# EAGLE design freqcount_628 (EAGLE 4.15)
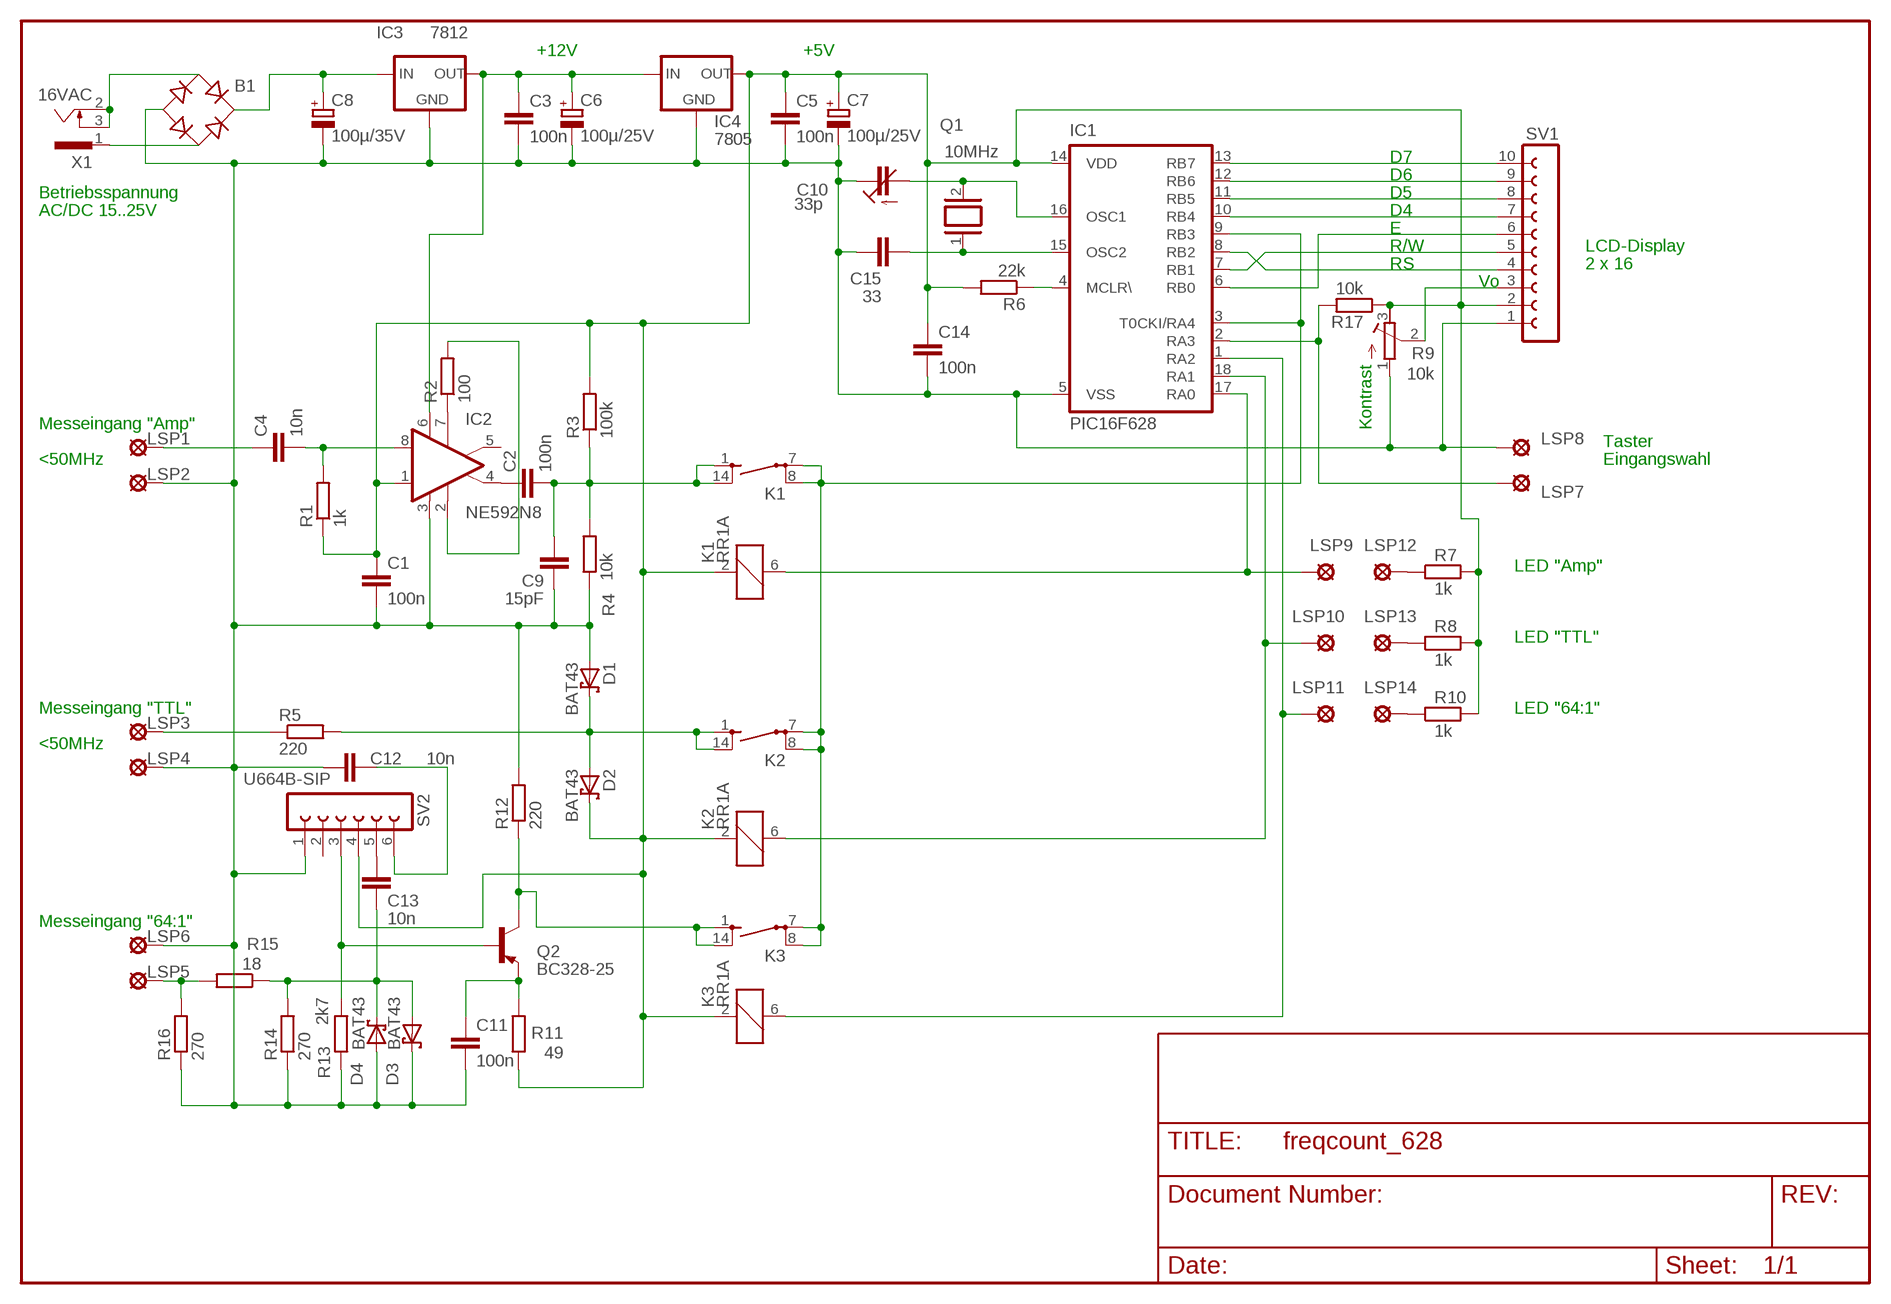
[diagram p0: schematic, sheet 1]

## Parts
B1  RB1A  [RB1A]
C1  100n  C-EU050-025X075  [C050-025X075]
C2  100n  C-EU050-025X075  [C050-025X075]
C3  100n  C-EU050-025X075  [C050-025X075]
C4  10n  C-EU050-025X075  [C050-025X075]
C5  100n  C-EU050-025X075  [C050-025X075]
C6  100µ/25V  CPOL-EUE5-8.5  [E5-8,5]
C7  100µ/25V  CPOL-EUE5-8.5  [E5-8,5]
C8  100µ/35V  CPOL-EUE5-8.5  [E5-8,5]
C9  15pF  C-EU050-025X075  [C050-025X075]
C10  33p  C-TRIMM3040.427  [CTRIM3040.427]
C11  100n  C-EU050-025X075  [C050-025X075]
C12  10n  C-EU050-025X075  [C050-025X075]
C13  10n  C-EU050-025X075  [C050-025X075]
C14  100n  C-EU050-025X075  [C050-025X075]
C15  33  C-EU025-025X050  [C025-025X050]
D1  BAT43  [DO35-10]
D2  BAT43  [DO35-10]
D3  BAT43  [DO35-10]
D4  BAT43  [DO35-10]
IC1  PIC16F628  PIC16F84AP  [DIL18]
IC2  NE592N8  [DIL08]
IC3  7812  78XXS  [78XXS]
IC4  7805  78XXS  [78XXS]
K1  RR1A  [RR1A]
K2  RR1A  [RR1A]
K3  RR1A  [RR1A]
LSP1  LSP10  [LSP10]
LSP2  LSP10  [LSP10]
LSP3  LSP10  [LSP10]
LSP4  LSP10  [LSP10]
LSP5  LSP10  [LSP10]
LSP6  LSP10  [LSP10]
LSP7  LSP10  [LSP10]
LSP8  LSP10  [LSP10]
LSP9  LSP10  [LSP10]
LSP10  LSP10  [LSP10]
LSP11  LSP10  [LSP10]
LSP12  LSP10  [LSP10]
LSP13  LSP10  [LSP10]
LSP14  LSP10  [LSP10]
Q1  10MHz  XTAL/S  [QS]
Q2  BC328-25  [TO92-EBC]
R1  1k  R-EU_0207/10  [0207/10]
R2  100  R-EU_0207/10  [0207/10]
R3  100k  R-EU_0207/10  [0207/10]
R4  10k  R-EU_0207/10  [0207/10]
R5  220  R-EU_0207/10  [0207/10]
R6  22k  R-EU_0207/10  [0207/10]
R7  1k  R-EU_0207/10  [0207/10]
R8  1k  R-EU_0207/10  [0207/10]
R9  10k  R-TRIMM3339P  [RTRIM3339P]
R10  1k  R-EU_0207/10  [0207/10]
R11  49  R-EU_0207/10  [0207/10]
R12  220  R-EU_0207/10  [0207/10]
R13  2k7  R-EU_0207/10  [0207/10]
R14  270  R-EU_0207/10  [0207/10]
R15  18  R-EU_0207/10  [0207/10]
R16  270  R-EU_0207/10  [0207/10]
R17  10k  R-EU_0207/10  [0207/10]
SV1  FE10-1  [FE10]
SV2  U664B-SIP  FE06-1  [FE06]
X1  16VAC  733989-55  [733989-5]

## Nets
5VDC: C1.1 C5.1 C7.+ C14.1 D2.C IC1.14(VDD) IC2.1(IN2) IC4.OUT K1.2 K2.2 K3.2 R1.1 R3.2 R6.2 R7.2 R8.2 R9.3(A) R10.2 R11.1 R17.1 SV1.2 SV2.4
12VDC: C3.1 C6.+ IC2.6(V+) IC3.OUT IC4.IN
GND: B1.- C1.2 C3.2 C5.2 C6.- C7.- C8.- C9.1 C10.1A(E) C11.2 C12.1 C14.2 C15.1 D1.A D3.C D4.A IC1.5(VSS) IC2.3(V-) IC3.GND IC4.GND LSP2.MP LSP4.MP LSP6.MP LSP8.MP R4.1 R9.1(E) R12.2 R13.1 R14.1 R16.1 SV1.1 SV2.1
N$1: C4.2 IC2.8(IN1) R1.2
N$2: C4.1 LSP1.MP
N$3: C2.1 IC2.4(OUT2)
N$5: IC2.7(G1A) R2.1
N$6: IC2.2(G1B) R2.2
N$7: LSP3.MP R5.1
N$8: C2.2 C9.2 K1.1(2:S) K1.14(2:S) R3.1 R4.2
N$9: D1.C D2.A K2.1(2:S) K2.14(2:S) R5.2
N$10: C15.2 IC1.15(OSC2) Q1.1
N$11: C10.2(A) IC1.16(OSC1) Q1.2
N$12: B1.+ C8.+ IC3.IN
N$13: IC1.4(MCLR\) R6.1
N$14: IC1.13(RB7) SV1.10
N$15: IC1.12(RB6) SV1.9
N$16: B1.AC2 X1.1
N$17: B1.AC1 X1.2 X1.3
N$18: IC1.11(RB5) SV1.8
N$19: IC1.10(RB4) SV1.7
N$20: R9.2(S) SV1.3
N$21: IC1.8(RB2) SV1.4
N$22: IC1.7(RB1) SV1.5
N$23: IC1.6(RB0) SV1.6
N$24: IC1.17(RA0) K1.6 LSP9.MP
N$25: IC1.18(RA1) K2.6 LSP10.MP
N$26: IC1.1(RA2) K3.6 LSP11.MP
N$27: LSP12.MP R7.1
N$28: C13.2 D3.A D4.C R14.2 R15.1
N$29: LSP13.MP R8.1
N$30: C11.1 Q2.E R11.2
N$31: LSP14.MP R10.1
N$32: K3.1(2:S) K3.14(2:S) Q2.C R12.1
N$33: IC1.2(RA3) LSP7.MP R17.2
N$34: C13.1 SV2.5
N$35: C12.2 SV2.6
N$36: Q2.B R13.2 SV2.3
N$37: LSP5.MP R15.2 R16.2
TAKTRA4: IC1.3(T0CKI/RA4) IC1.9(RB3) K1.7(2:P) K1.8(2:P) K2.7(2:P) K2.8(2:P) K3.7(2:P) K3.8(2:P)
Unconnected: IC2.5(OUT1) SV2.2

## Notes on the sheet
- +12V | +5V
- D7
- D6
- Betriebsspannung | D5
- AC/DC 15..25V | D4
- E
- R/W | LCD-Display
- RS | 2 x 16
- Vo
- Messeingang "Amp" | Kontrast
- Taster
- <50MHz | Eingangswahl
- LED "Amp"
- LED "TTL"
- Messeingang "TTL" | LED "64:1"
- <50MHz
- Messeingang "64:1"

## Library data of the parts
B1 = rectifier:RB1A: RECTIFIER 1 A
C1-C5 C9 C11-C15 = rcl:C-EU: CAPACITOR, European symbol
C6-C8 = rcl:CPOL-EU: POLARIZED CAPACITOR, European symbol
C10 = rcl:C-TRIMM: Trimm capacitor
D1-D4 = sprut:BAT43: DIODE
IC1 = microchip:PIC16F8*: MICROCONTROLLER 8-Bit PIC16F8X Family - CMOS Flash/EEPROM Pin Compatible : PIC16F83, PIC16CR83, PIC16F84A, PIC16CR84 see also PIC16C*
IC2 = linear:NE592?8: VIDEO AMPLIFIER
IC3 IC4 = v-reg:78XXS: VOLTAGE REGULATOR
K1-K3 = relay:RR1A: RELAY reed, polarity, 1 x norm. open with shield
LSP1-LSP14 = solpad:LSP10: SOLDER PAD
Q1 = special:XTAL/S: CRYSTAL
Q2 = transistor-pnp:BC328*: PNP Transistror
R1-R8 R10-R17 = rcl:R-EU_: RESISTOR, European symbol
R9 = rcl:R-TRIMM: Trimm resistor
SV1 = con-lsta:FE10-1: FEMALE HEADER
SV2 = con-lsta:FE06-1: FEMALE HEADER
X1 = con-conrad:733989-55: FEMALE PRINT CONNECTOR 1.1 mm, FUK HING Industries, distributor Conrad

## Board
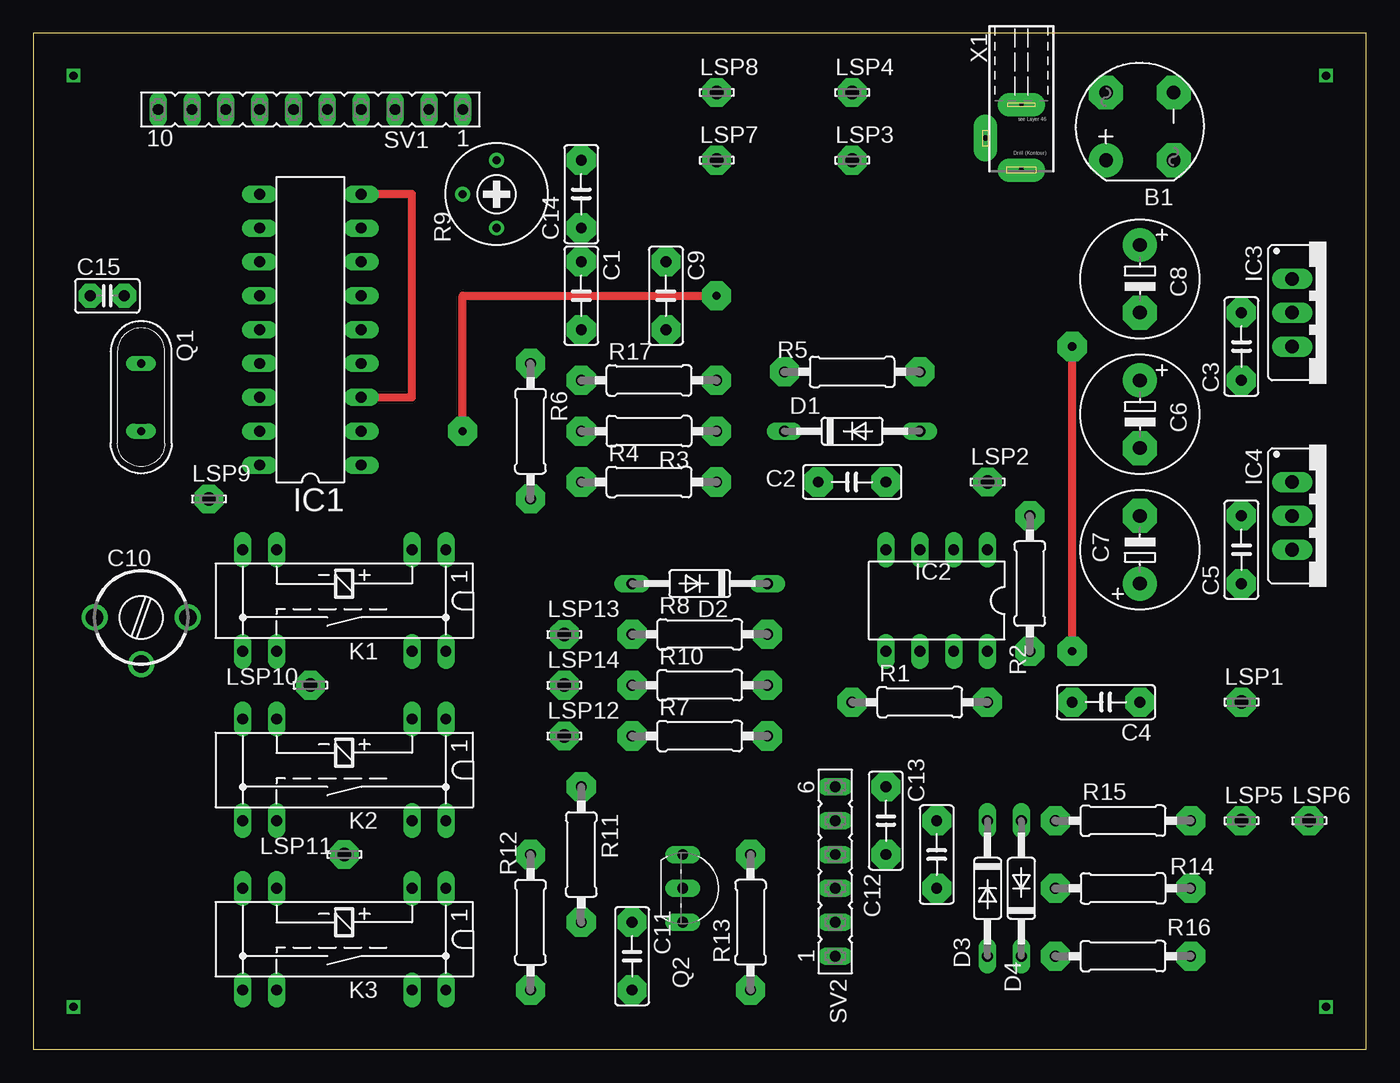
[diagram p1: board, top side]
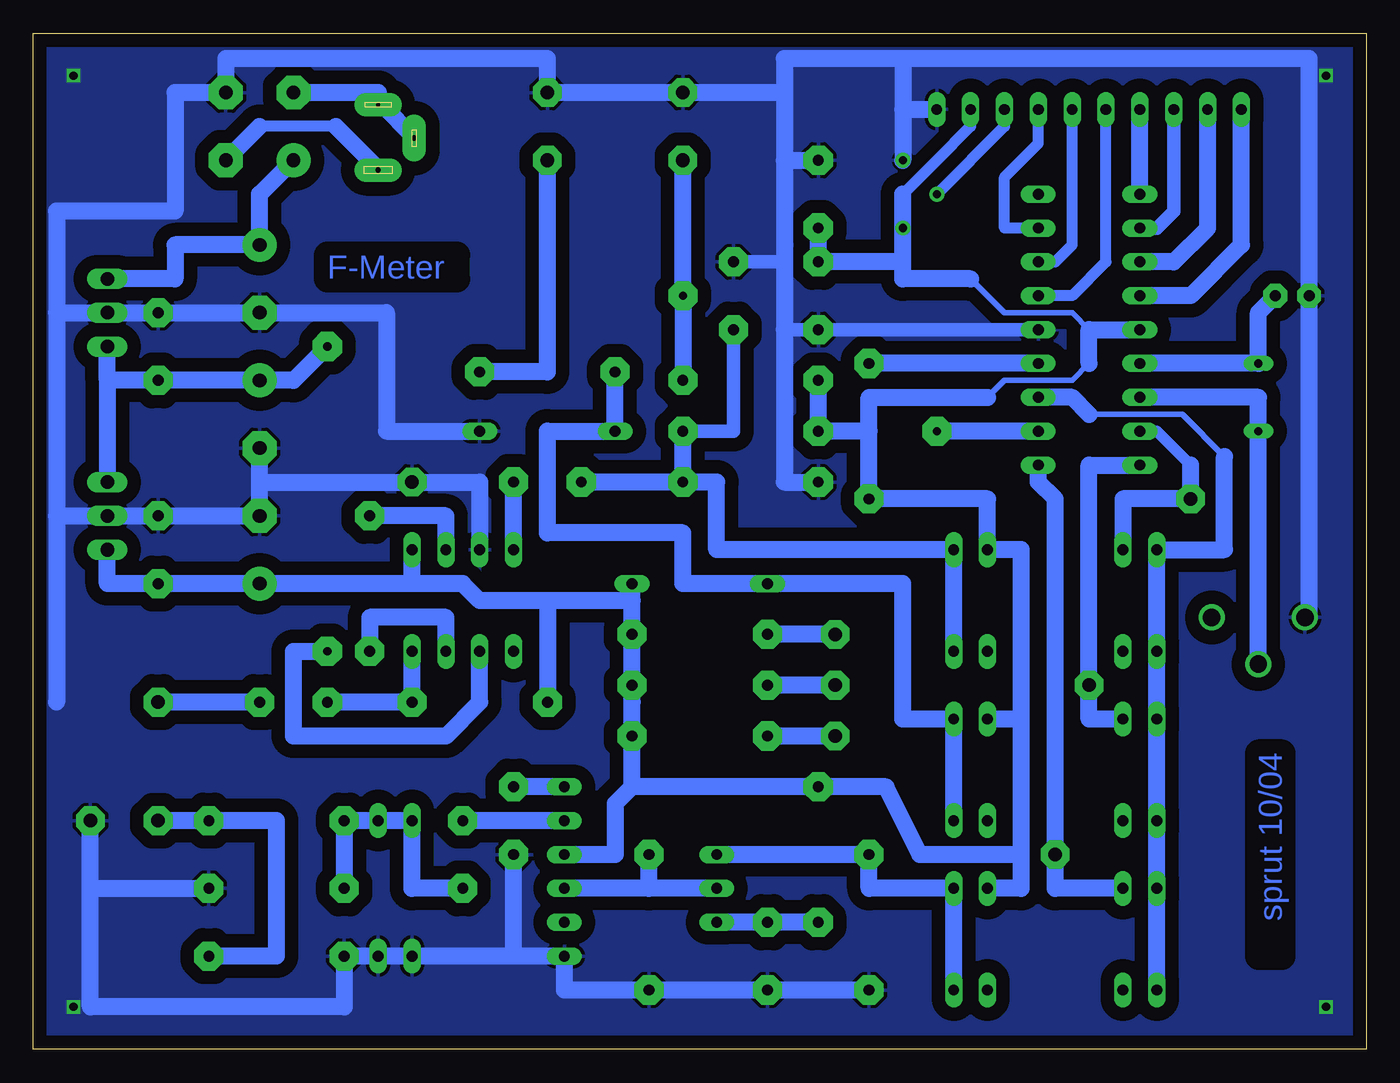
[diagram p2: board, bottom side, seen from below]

Size 100 x 76.19 mm. Coordinates in mm from the lower left corner, seen from the top.
Outline: 0,0 100,0 100,76.19 0,76.19 0,0
Copper layers (1*16): Top 0.035mm / dielectric 1.5mm / Bottom 0.035mm
Design rules "default": minimum track width 10mil, minimum drill 24mil, track to track 8mil, track to pad 8mil, pad to pad 8mil, via to via 8mil, smd to smd 8mil, copper to edge 40mil, drill to drill 8mil, minimum pad ring 10mil, minimum via ring 8mil, stop-mask expansion 4mil, vias tented up to drill 0mil, thermal gap 10mil

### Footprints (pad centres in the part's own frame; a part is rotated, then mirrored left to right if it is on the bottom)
RB1A = drill 1.016 pad 2.54 round: + -2.54,2.54 | drill 1.016 pad 2.54 octagon: - 2.54,-2.54; AC1 2.54,2.54; AC2 -2.54,-2.54
C050-025X075 = drill 0.813 pad 2.184 octagon: 1 -2.54,0; 2 2.54,0
E5-8,5 = drill 1.016 pad 2.54 round: + -2.54,0 | drill 1.016 pad 2.54 octagon: - 2.54,0
CTRIM3040.427 = drill 1.3 round: 1A -3.5,0; 1B 3.5,0; 2 0,-3.5
C025-025X050 = drill 0.813 pad 1.778 octagon: 1 -1.27,0; 2 1.27,0
DO35-10 = drill 0.813 long: A 5.08,0; C -5.08,0
DIL18 = drill 0.813 long: 1 -10.16,-3.81; 2 -7.62,-3.81; 3 -5.08,-3.81; 4 -2.54,-3.81; 5 0,-3.81; 6 2.54,-3.81; 7 5.08,-3.81; 8 7.62,-3.81; 9 10.16,-3.81; 10 10.16,3.81; 11 7.62,3.81; 12 5.08,3.81; 13 2.54,3.81; 14 0,3.81; 15 -2.54,3.81; 16 -5.08,3.81; 17 -7.62,3.81; 18 -10.16,3.81
DIL08 = drill 0.813 long: 1 -3.81,-3.81; 2 -1.27,-3.81; 3 1.27,-3.81; 4 3.81,-3.81; 5 3.81,3.81; 6 1.27,3.81; 7 -1.27,3.81; 8 -3.81,3.81
78XXS = drill 1.016 long: GND 0,-2.54; IN -2.54,-2.54; OUT 2.54,-2.54
RR1A = drill 0.813 long: 1 -7.62,-3.81; 2 -5.08,-3.81; 6 5.08,-3.81; 7 7.62,-3.81; 8 7.62,3.81; 9 5.08,3.81; 13 -5.08,3.81; 14 -7.62,3.81
LSP10 = drill 1.016 pad 2.159 octagon: MP 0,0
QS = drill 0.61 long: 1 -2.54,0; 2 2.54,0
TO92-EBC = drill 0.813 long: B 0,-1.27; C -2.54,-1.27; E 2.54,-1.27
0207/10 = drill 0.813 pad 2.184 octagon: 1 -5.08,0; 2 5.08,0
RTRIM3339P = drill 0.61 round: 1 -2.54,0; 2 0,-2.54; 3 2.54,0
FE10 = drill 0.813 long: 1 -11.43,0; 2 -8.89,0; 3 -6.35,0; 4 -3.81,0; 5 -1.27,0; 6 1.27,0; 7 3.81,0; 8 6.35,0; 9 8.89,0; 10 11.43,0
FE06 = drill 0.813 long: 1 -6.35,0; 2 -3.81,0; 3 -1.27,0; 4 1.27,0; 5 3.81,0; 6 6.35,0
733989-5 = drill 0.4 pad 1.778 long: 1 0,5.82; 3 2.7,3.42 | drill 0.3 pad 1.778 long: 2 0,0.92

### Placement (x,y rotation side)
B1  83.02,69.21 90 top
C1  41.11,56.51 270 top
C2  61.43,42.54 180 top
C3  90.64,52.7 90 top
C4  80.48,26.03 180 top
C5  90.64,37.46 90 top
C6  83.02,47.62 270 top
C7  83.02,37.46 90 top
C8  83.02,57.78 270 top
C9  47.46,56.51 270 top
C10  8.09,32.38 0 top
C11  44.92,6.98 270 top
C12  63.97,17.14 90 top
C13  67.78,14.6 270 top
C14  41.11,64.13 90 top
C15  5.55,56.51 0 top
D1  61.43,46.35 0 top
D2  50,34.92 180 top
D3  74.13,12.06 90 top
D4  71.59,12.06 270 top
IC1  20.79,53.97 90 top
IC2  67.78,33.65 180 top
IC3  96.99,55.24 270 top
IC4  96.99,40 270 top
K1  23.33,33.65 180 top
K2  23.33,20.95 180 top
K3  23.33,8.25 180 top
LSP1  90.64,26.03 0 top
LSP2  71.59,42.54 0 top
LSP3  61.43,66.67 0 top
LSP4  61.43,71.75 0 top
LSP5  90.64,17.14 0 top
LSP6  95.72,17.14 0 top
LSP7  51.27,66.67 0 top
LSP8  51.27,71.75 0 top
LSP9  13.17,41.27 0 top
LSP10  20.79,27.3 0 top
LSP11  23.33,14.6 0 top
LSP12  39.84,23.49 0 top
LSP13  39.84,31.11 0 top
LSP14  39.84,27.3 0 top
Q1  8.09,48.89 270 top
Q2  50,12.06 270 top
R1  66.51,26.03 0 top
R2  74.77,34.92 90 top
R3  46.19,46.35 180 top
R4  46.19,42.54 0 top
R5  61.43,50.8 180 top
R6  37.3,46.35 270 top
R7  50,23.49 0 top
R8  50,31.11 0 top
R9  34.76,64.13 270 top
R10  50,27.3 0 top
R11  41.11,14.6 270 top
R12  37.3,9.52 270 top
R13  53.81,9.52 90 top
R14  81.75,12.06 180 top
R15  81.75,17.14 0 top
R16  81.75,6.98 0 top
R17  46.19,50.16 0 top
SV1  20.79,70.48 180 top
SV2  60.16,13.33 90 top
X1  74.13,71.75 180 top

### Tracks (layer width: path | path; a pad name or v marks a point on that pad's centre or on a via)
5VDC
  Bottom 0.406: 55.08,26.03 R10.2 R8.2 | 20.79,51.43 22.06,50.16 27.14,50.16 28.41,48.89 | 20.79,53.97 22.06,55.24 27.14,55.24 29.68,57.78
  Bottom 0.813: SV1.2 29.68,69.21 32.22,66.67 34.76,64.13
  Bottom 1.016: R3.2 R17.1
  Bottom 1.27: 55.08,19.68 R11.1 36.03,19.68 33.49,14.6 25.87,14.6 | 55.08,19.68 R7.2 55.08,26.03 R8.2 55.08,33.65 | IC4.OUT 94.45,34.92 C5.1 C7.+ 71.59,34.92 | R17.1 R3.2 37.3,46.35 | 25.87,14.6 25.87,12.06 K3.2 | 25.87,14.6 25.87,24.76 | 25.87,24.76 K2.2 | 25.87,24.76 25.87,37.46 K1.2 28.41,41.27 R6.2 37.3,46.35 | IC1.14 20.79,53.97 20.79,51.43 | 34.76,64.13 R9.3 34.76,59.05 | 71.59,34.92 IC2.1 | 71.59,34.92 67.78,34.92 66.51,33.65 61.43,33.65 | 55.08,33.65 61.43,33.65 | 55.08,33.65 D2.C | SV2.4 56.35,14.6 56.35,18.41 55.08,19.68 | 29.68,57.78 34.76,57.78 34.76,59.05 | C14.1 C1.1 34.76,59.05 | 28.41,48.89 37.3,48.89 37.3,46.35 | 61.43,33.65 R1.1
12VDC  (via drill 0.61 pad 2.18)
  Top 0.61: v77.94,29.84 v77.94,52.7
  Bottom 1.27: 94.45,50.16 IC3.OUT | 94.45,50.16 C3.1 C6.+ 80.48,50.16 v77.94,52.7 | 94.45,50.16 IC4.IN | IC2.6 66.51,26.03 69.05,23.49 80.48,23.49 80.48,29.84 v77.94,29.84
GND  (via drill 0.61)
  Bottom 0.406: C10.1A 4.28,32.38
  Bottom 1.016: IC1.5 C1.2 43.65,53.97 | 43.65,59.05 C9.1
  Bottom 1.27: 63.97,6.98 SV2.1 60.16,4.44 R13.1 R12.2 C11.2 | 63.97,6.98 D4.A D3.C R16.1 76.67,3.17 95.72,3.17 95.72,12.06 | 63.97,6.98 C12.1 | 95.72,12.06 LSP6.MP | 95.72,12.06 R14.1 | D1.A 73.5,46.35 73.5,55.24 C8.- C3.2 IC3.GND 98.26,55.24 | 83.02,42.54 C7.- C5.2 IC4.GND 98.26,40 | 83.02,42.54 C6.- | 98.26,55.24 98.26,40 | 98.26,40 98.26,26.03 | 43.65,71.75 LSP8.MP LSP4.MP 61.43,74.29 85.56,74.29 B1.- 89.37,71.75 89.37,62.86 98.26,62.86 98.26,55.24 | 43.65,71.75 43.65,66.67 | R4.1 43.65,42.54 43.65,53.97 43.65,59.05 43.65,66.67 | 34.76,70.48 R9.1 | 34.76,74.29 4.28,74.29 C15.1 4.28,32.38 | 34.76,74.29 34.76,70.48 | 34.76,70.48 SV1.1 | 34.76,74.29 43.65,74.29 43.65,71.75 | 43.65,66.67 C14.2 | IC2.3 66.51,42.54 83.02,42.54
  other vias: 3.01,73.02 3.01,3.17 96.99,73.02 96.99,3.17
  pour Bottom (isolate 1.016): -0.8,76.83 100.8,76.83 100.8,-0.64 -0.8,-0.64
N$1
  Bottom 1.27: IC2.8 R1.2 C4.2
N$2
  Bottom 1.27: C4.1 LSP1.MP
N$3
  Bottom 1.27: IC2.4 C2.1
N$5
  Bottom 1.27: IC2.7 69.05,32.38 74.77,32.38 R2.1
N$6
  Bottom 1.27: IC2.2 69.05,40 R2.2
N$7
  Bottom 1.27: LSP3.MP 61.43,50.8 R5.1
N$8
  Bottom 1.016: C9.2 47.46,46.35 R3.1
  Bottom 1.27: R4.2 R3.1 | K1.14 K1.1 48.73,37.46 48.73,42.54 R4.2 | R4.2 C2.2
N$9
  Bottom 1.27: R5.2 D1.C 61.43,46.35 61.43,38.73 51.27,38.73 51.27,34.92 D2.A 34.76,34.92 34.76,24.76 K2.1 K2.14
N$10
  Bottom 1.27: IC1.15 Q1.1 8.09,55.24 C15.2
N$11
  Bottom 0.406: C10.2 8.09,33.65
  Bottom 1.27: IC1.16 8.09,48.89 Q1.2 C10.2
N$12
  Bottom 1.27: IC3.IN 89.37,57.78 89.37,60.32 C8.+ 83.02,64.13 B1.+
N$13
  Bottom 1.27: IC1.4 R6.1
N$14
  Bottom 1.27: SV1.10 9.36,60.32 13.17,56.51 IC1.13
N$15
  Bottom 1.27: SV1.9 11.9,61.59 14.44,59.05 IC1.12
N$16
  Bottom 0.406: X1.1 74.13,66.03
  Bottom 0.813: 77.3,69.21 83.02,69.21
  Bottom 1.27: 83.02,69.21 B1.AC2 | 74.13,66.03 77.3,69.21
N$17
  Bottom 0.406: X1.3 71.43,68.41 | 73.84,70.83 X1.2
  Bottom 1.27: B1.AC1 74.13,71.75 X1.2 | 71.43,68.41 73.84,70.83
N$18
  Bottom 1.016: SV1.8 14.44,62.86 15.71,61.59 IC1.11
N$19
  Bottom 1.27: IC1.10 SV1.7
N$20
  Bottom 0.813: R9.2 27.14,69.21 SV1.3
N$21
  Bottom 0.813: SV1.4 24.6,67.94 27.14,65.4 27.14,61.59 IC1.8
N$22
  Bottom 0.813: SV1.5 22.06,60.32 23.33,59.05 IC1.7
N$23
  Bottom 0.813: IC1.6 22.06,56.51 19.52,59.05 SV1.6
N$24
  Bottom 0.813: 13.17,43.81 15.71,46.35 IC1.17
  Bottom 1.27: K1.6 18.25,41.27 LSP9.MP 13.17,43.81
N$25
  Bottom 1.27: K2.6 20.79,24.76 LSP10.MP 20.79,43.81 IC1.18
N$26
  Bottom 1.27: K3.6 23.33,12.06 LSP11.MP 23.33,41.27 24.6,42.54 IC1.1
N$27
  Bottom 1.27: LSP12.MP R7.1
N$28
  Bottom 1.27: R14.2 R15.1 D3.A D4.C 71.59,12.06 C13.2
N$29
  Bottom 1.27: LSP13.MP R8.1
N$30
  Bottom 1.27: R11.2 C11.1 Q2.E
N$31
  Bottom 1.27: LSP14.MP R10.1
N$32
  Bottom 1.27: K3.14 K3.1 37.3,12.06 R12.1 Q2.C
N$33  (via drill 0.61 pad 2.18)
  Top 0.61: v32.22,46.35 32.22,56.51 v51.27,56.51
  Bottom 1.27: R17.2 v51.27,56.51 LSP7.MP | IC1.2 v32.22,46.35
N$34
  Bottom 1.27: SV2.5 C13.1
N$35
  Bottom 1.27: SV2.6 C12.2
N$36
  Bottom 1.27: Q2.B 53.81,12.06 | 53.81,12.06 SV2.3 | 53.81,12.06 R13.2
N$37
  Bottom 1.27: LSP5.MP R15.2 81.75,17.14 81.75,6.98 R16.2
TAKTRA4
  Top 0.61: IC1.9 28.41,64.13 28.41,48.89 IC1.3
  Bottom 0.406: 10.63,44.45 13.81,47.62 20.79,47.62
  Bottom 1.27: K3.8 K3.7 K2.8 K2.7 K1.8 K1.7 10.63,37.46 10.63,44.45 | IC1.3 22.06,48.89 20.79,47.62

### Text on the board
Bottom: F-Meter | sprut 10/04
